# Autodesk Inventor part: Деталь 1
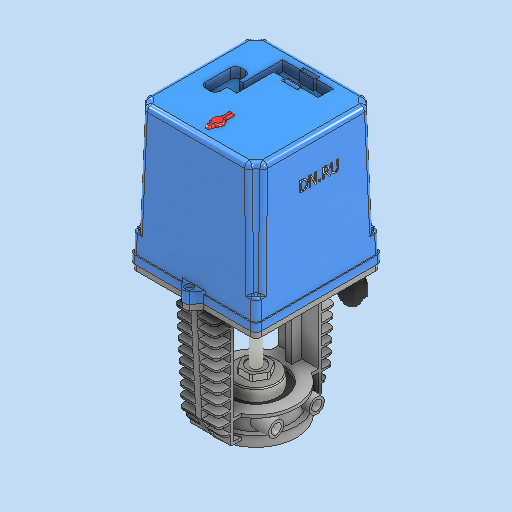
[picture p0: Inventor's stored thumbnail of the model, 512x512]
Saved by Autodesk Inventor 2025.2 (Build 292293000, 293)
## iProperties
Created: 2026-04
Part Number: Деталь 1
Material: Типовые
Document SubType Name: Modeling
Designer: igorr
Density: 1 g/cm^3
Appearance: По умолчанию
Author: igorr
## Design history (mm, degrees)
sketch "Эскиз1"
  geometry: L1 (-62.5, 62.5)-(-62.5, -62.5); L2 (-62.5, -62.5)-(62.5, -62.5); L3 (62.5, -62.5)-(62.5, 62.5); L4 (62.5, 62.5)-(-62.5, 62.5); L5 (-62.5, 62.5)-(62.5, -62.5); L6 (-62.5, -62.5)-(62.5, 62.5); L7 (0, 0)-(0, -71.5); L8 (0, -62.5)-(0, -71.5); L9 (0, 0)-(25.646, 0); L10 (0, -71.5)-(0, -61.5); C1 r 5 at (0, 66.5); 5 further points
  constraints: 20 end point, 6 midpoint, 2 parallel, 2 perpendicular, 2 point on line, 2 vertical, 1 centre point, 1 collinear, 1 symmetric about line, 4 other
  dimensions: "d0" = 125 distance of L1.start L1.end; "d1" = 125 distance of L2.end L1.end; "d2" = 71.5 distance of L7.start L7.end; "d5" = 10 distance of L7.end L10.end
extrude "Выдавливание1" new body sketch "Эскиз1" distance "d3" = 6; taper "d4" = 0 deg
chamfer "Фаска1" distance "d6" = 7.25; stored, may be unused: second distance "d7" = 2, angle "d8" = 45 deg
sketch "Эскиз2"
  geometry: L1 (-62.5, 62.5)-(-62.5, -62.5) reference; L2 (-62.5, -62.5)-(-10.25, -62.5) reference; L3 (-3.841, -69.701)-(-10.25, -62.5) reference; L4 (10.25, -62.5)-(3.841, -69.701) reference; L5 (10.25, -62.5)-(62.5, -62.5) reference; L6 (62.5, -62.5)-(62.5, 62.5) reference; L7 (62.5, 62.5)-(10.25, 62.5) reference; L8 (3.841, 69.701)-(10.25, 62.5) reference; L9 (-10.25, 62.5)-(-3.841, 69.701) reference; L10 (-10.25, 62.5)-(-62.5, 62.5) reference; L11 (61.5, 61.5)-(61.5, -61.5); L12 (61.5, -61.5)-(9.801, -61.5); L13 (9.801, -61.5)-(3.083, -69.049); L14 (-3.083, -69.049)-(-9.801, -61.5); L15 (-9.801, -61.5)-(-61.5, -61.5); L16 (-61.5, -61.5)-(-61.5, 61.5); L17 (-61.5, 61.5)-(-9.801, 61.5); L18 (-9.801, 61.5)-(-3.083, 69.049); L19 (3.083, 69.049)-(9.801, 61.5); L20 (9.801, 61.5)-(61.5, 61.5); A1 r 5 centre (0, -66.5) between (-3.841, -69.701) and (3.841, -69.701) reference; A2 r 5 centre (0, 66.5) between (3.841, 69.701) and (-3.841, 69.701) reference; A3 r 4 centre (0, -66.5) between (-3.083, -69.049) and (3.083, -69.049); A4 r 4 centre (0, 66.5) between (3.083, 69.049) and (-3.083, 69.049); 1 further point
  constraints: 20 end point, 4 point on circle, 2 centre point, 11 other
  dimensions: "d9" = 1 distance between parallel lines of L6 L11
extrude "Выдавливание2" cut sketch "Эскиз2" distance "d10" = 21; taper "d11" = 0 deg
sketch "Эскиз3"
  geometry: L1 (61.5, 61.5)-(9.801, 61.5) reference; L2 (9.801, 61.5)-(3.083, 69.049) reference; L3 (-3.083, 69.049)-(-9.801, 61.5) reference; L4 (-9.801, 61.5)-(-61.5, 61.5) reference; L5 (-61.5, 61.5)-(-61.5, -61.5) reference; L6 (-61.5, -61.5)-(-9.801, -61.5) reference; L7 (-9.801, -61.5)-(-3.083, -69.049) reference; L8 (3.083, -69.049)-(9.801, -61.5) reference; L9 (9.801, -61.5)-(61.5, -61.5) reference; L10 (61.5, -61.5)-(61.5, 61.5) reference; L11 (62.5, -62.5)-(10.25, -62.5); L12 (10.25, -62.5)-(3.841, -69.701); L13 (-3.841, -69.701)-(-10.25, -62.5); L14 (-10.25, -62.5)-(-62.5, -62.5); L15 (-62.5, -62.5)-(-62.5, 62.5); L16 (-62.5, 62.5)-(-10.25, 62.5); L17 (-10.25, 62.5)-(-3.841, 69.701); L18 (3.841, 69.701)-(10.25, 62.5); L19 (10.25, 62.5)-(62.5, 62.5); L20 (62.5, 62.5)-(62.5, -62.5); A1 r 4 centre (0, 66.5) between (3.083, 69.049) and (-3.083, 69.049) reference; A2 r 4 centre (0, -66.5) between (-3.083, -69.049) and (3.083, -69.049) reference; A3 r 5 centre (0, -66.5) between (-3.841, -69.701) and (3.841, -69.701); A4 r 5 centre (0, 66.5) between (3.841, 69.701) and (-3.841, 69.701); 1 further point
  constraints: 20 end point, 4 point on circle, 2 centre point, 11 other
  dimensions: "d12" = 1 distance between parallel lines of L9 L11
extrude "Выдавливание3" join sketch "Эскиз3" distance "d13" = 8; taper "d14" = 0 deg
sketch "Эскиз4"
  geometry: L1 (61.5, -61.5)-(61.5, 61.5); L2 (61.5, 61.5)-(-61.5, 61.5); L3 (-61.5, 61.5)-(-61.5, -61.5); L4 (-61.5, -61.5)-(61.5, -61.5); L5 (61.5, -61.5)-(-61.5, 61.5); L6 (61.5, 61.5)-(-61.5, -61.5); 1 further point
  constraints: 12 end point, 2 midpoint, 2 parallel, 1 perpendicular, 1 vertical
  dimensions: "d15" = 123 distance of L1.start L1.end; "d16" = 123 distance of L2.end L1.end
extrude "Выдавливание4" join sketch "Эскиз4" distance "d17" = 130; taper "d18" = -1 deg
sketch "Эскиз5"
  geometry: L1 (61.5, 61.5)-(61.5, -61.5) reference; L2 (61.5, -61.5)-(-61.5, -61.5) reference; L3 (-61.5, -61.5)-(-61.5, 61.5) reference; L4 (-61.5, 61.5)-(61.5, 61.5) reference; L5 (-3.841, 69.701)-(-10.25, 62.5) reference; L6 (-10.25, 62.5)-(-62.5, 62.5) reference; L7 (-62.5, 62.5)-(-62.5, -62.5) reference; L8 (-62.5, -62.5)-(-10.25, -62.5) reference; L9 (-10.25, -62.5)-(-3.841, -69.701) reference; L10 (3.841, -69.701)-(10.25, -62.5) reference; L11 (10.25, -62.5)-(62.5, -62.5) reference; L12 (62.5, -62.5)-(62.5, 62.5) reference; L13 (62.5, 62.5)-(10.25, 62.5) reference; L14 (10.25, 62.5)-(3.841, 69.701) reference; L15 (10.25, 62.5)-(14.397, 57.84); L16 (14.397, 57.84)-(-14.397, 57.84); L17 (-14.397, 57.84)-(-10.25, 62.5); L18 (62.5, 0)-(81.182, 0); L19 (10.25, -62.5)-(3.841, -69.701); L20 (-3.841, -69.701)-(-10.25, -62.5); L21 (14.397, -57.84)-(-14.397, -57.84); L22 (10.25, -62.5)-(14.397, -57.84); L23 (-14.397, -57.84)-(-10.25, -62.5); C1 r 4 at (0, 66.101); C2 r 4 at (0, -66.101); A1 r 5 centre (0, -66.5) between (-3.841, -69.701) and (3.841, -69.701) reference; A2 r 5 centre (0, 66.5) between (3.841, 69.701) and (-3.841, 69.701) reference; A3 r 5 centre (0, -66.5) between (-3.841, -69.701) and (3.841, -69.701); 1 further point
  constraints: 18 end point, 4 symmetric about line, 3 centre point, 2 horizontal, 2 point on circle, 2 point on line, 1 collinear, 1 midpoint, 2 other
  dimensions: "d19" = 8 diameter of C1
extrude "Выдавливание5" join sketch "Эскиз5" distance "d20" = 3; taper "d21" = 0 deg
sketch "Эскиз6"
  geometry: L1 (-59.231, 59.231)-(59.231, 59.231) reference; C1 r 7.5 at (59.231, 59.231); C2 r 7.5 at (-59.231, 59.231); C3 r 7.5 at (-59.231, -59.231); C4 r 7.5 at (59.231, -59.231); 1 further point
  constraints: 4 centre point, 9 other
  dimensions: "d22" = 15 diameter of C1; "d25" = 360 deg dimension on point (0, 0) L1.end (derived)
extrude "Выдавливание6" cut sketch "Эскиз6" distance "d27" = 110; taper "d28" = -2 deg
sketch "Эскиз7"
  geometry: L1 (-21.282, 47.681)-(28.718, 47.681); L2 (28.718, 47.681)-(28.718, 32.681); L3 (28.718, 32.681)-(-21.282, 32.681); L4 (-21.282, 32.681)-(-21.282, 47.681); L5 (-21.282, 47.681)-(28.718, 32.681); L6 (28.718, 47.681)-(-21.282, 32.681); L7 (-40.282, 15)-(-40.282, -10); L8 (-35.282, -15)-(-30.282, -15); L9 (-25.282, -10)-(-25.282, 15); L10 (-30.282, 20)-(-35.282, 20); L11 (-40.282, 20)-(-25.282, -15); L12 (-40.282, -15)-(-25.282, 20); L13 (-35.282, 8.5)-(-15.282, 8.5); L14 (-15.282, 8.5)-(-15.282, -3.5); L15 (-15.282, -3.5)-(-35.282, -3.5); L16 (-35.282, -3.5)-(-35.282, 8.5); L17 (-35.282, 8.5)-(-15.282, -3.5); L18 (-15.282, 8.5)-(-35.282, -3.5); L19 (-15.282, -3.5)-(-21.282, -3.5); L20 (-21.282, -3.5)-(-21.282, 50.128); L21 (-21.282, 50.128)-(-15.282, 50.128); L22 (-15.282, 50.128)-(-15.282, -3.5); L23 (-4.282, 51.181)-(-4.282, 29.181); L24 (-4.282, 29.181)-(11.718, 29.181); L25 (11.718, 29.181)-(11.718, 51.181); L26 (11.718, 51.181)-(-4.282, 51.181); L27 (-4.282, 51.181)-(11.718, 29.181); L28 (-4.282, 29.181)-(11.718, 51.181); A1 r 5 centre (-30.282, 15) between (-25.282, 15) and (-30.282, 20); A2 r 5 centre (-30.282, -10) between (-30.282, -15) and (-25.282, -10); A3 r 5 centre (-35.282, -10) between (-40.282, -10) and (-35.282, -15); A4 r 5 centre (-35.282, 15) between (-35.282, 20) and (-40.282, 15); 14 further points
  constraints: 56 end point, 10 parallel, 9 midpoint, 9 point on line, 8 point on circle, 8 tangent, 5 perpendicular, 4 centre point, 3 equal radius, 2 horizontal, 2 vertical, 1 collinear
  dimensions: "d29" = 50 distance of L1.start L1.end; "d30" = 15 distance of L1.end L2.end; "d31" = 35 distance of L11.start L12.start; "d32" = 15 distance of L11.end L12.start; "d33" = 20 distance of L13.start L13.end; "d34" = 12 distance of L13.end L14.end; "d35" = 6 distance of L14.end L19.end; "d36" = 22 distance of L23.start L23.end; "d37" = 16 distance of L24.end L23.end; "d38" = 5 radius of A1
extrude "Выдавливание7" cut sketch "Эскиз7" distance "d39" = 10; taper "d40" = 0 deg
sketch "Эскиз8"
  geometry: L1 (0, -46.285)-(0, -25.359); L2 (-15.282, 32.681)-(-15.282, -3.5) reference; L3 (3, -46.285)-(3, -25.359); L4 (-3, -25.359)-(-3, -46.285); C1 r 6 at (0, -38.032); A1 r 3 centre (0, -46.285) between (-3, -46.285) and (3, -46.285); A2 r 3 centre (0, -25.359) between (3, -25.359) and (-3, -25.359); 6 further points
  constraints: 8 end point, 4 point on circle, 4 tangent, 3 centre point, 2 parallel, 1 midpoint
  dimensions: "d41" = 12 diameter of C1; "d42" = 6 diameter of A2
extrude "Выдавливание8" join sketch "Эскиз8" distance "d43" = 2; taper "d44" = 0 deg
sketch "Эскиз9"
  geometry: L1 (-4.282, 51.181)-(11.718, 51.181) reference; L2 (11.718, 29.181)-(-4.282, 29.181) reference; L3 (11.718, 51.181)-(-4.282, 29.181); L4 (-3.282, 49.181)-(-3.282, 31.181); L5 (-3.282, 31.181)-(10.718, 31.181); L6 (10.718, 31.181)-(10.718, 49.181); L7 (10.718, 49.181)-(-3.282, 49.181); L8 (-3.282, 49.181)-(10.718, 31.181); L9 (-3.282, 31.181)-(10.718, 49.181); L10 (-3.282, 46.181)-(10.718, 46.181); L11 (10.718, 46.181)-(10.718, 34.181); L12 (10.718, 34.181)-(-3.282, 34.181); L13 (-3.282, 34.181)-(-3.282, 46.181); L14 (-3.282, 46.181)-(10.718, 34.181); L15 (10.718, 46.181)-(-3.282, 34.181); 6 further points
  constraints: 26 end point, 5 midpoint, 4 parallel, 2 perpendicular, 1 vertical
  dimensions: "d45" = 18 distance of L4.start L4.end; "d46" = 14 distance of L5.end L4.end; "d47" = 12 distance of L10.end L11.end
extrude "Выдавливание9" join sketch "Эскиз9" stored distance "d48" = 2; taper "d49" = 0 deg
sketch "Эскиз11"
  geometry: C1 r 22.5 at (0, 0); C2 r 25 at (0, 0); 1 further point
  constraints: 2 centre point, 1 coincident
  dimensions: "d50" = 45 diameter of C1; "d51" = 2.5 radial gap between concentric circles of C1 C2
extrude "Выдавливание10" cut sketch "Эскиз11" distance "d52" = 10; taper "d53" = 0 deg
sketch "Эскиз12"
  geometry: L1 (3, -61.5)-(3, 61.5); L2 (3, 61.5)-(-3, 61.5); L3 (-3, 61.5)-(-3, -61.5); L4 (-3, -61.5)-(3, -61.5); L5 (3, -61.5)-(-3, 61.5); L6 (3, 61.5)-(-3, -61.5); L7 (-9.801, 61.5)-(-61.5, 61.5) reference; L8 (3, -32.5)-(-3, -32.5); L9 (-3, -32.5)-(-3, 32.5); L10 (-3, 32.5)-(3, 32.5); L11 (3, 32.5)-(3, -32.5); L12 (3, -32.5)-(-3, 32.5); L13 (-3, -32.5)-(3, 32.5); L14 (20, -45.032)-(-20, -45.032); L15 (-20, -45.032)-(-20, -42.032); L16 (-20, -42.032)-(20, -42.032); L17 (20, -42.032)-(20, -45.032); L18 (20, -45.032)-(-20, -42.032); L19 (-20, -45.032)-(20, -42.032); L20 (-3, 0)-(-7.639, 0); L21 (20, 42.032)-(20, 45.032); L22 (-20, 42.032)-(20, 42.032); L23 (-20, 45.032)-(20, 42.032); L24 (20, 45.032)-(-20, 42.032); L25 (20, 45.032)-(-20, 45.032); L26 (-20, 45.032)-(-20, 42.032); 15 further points
  constraints: 50 end point, 9 midpoint, 7 parallel, 5 symmetric about line, 3 perpendicular, 2 collinear, 1 horizontal
  dimensions: "d54" = 6 distance of L2.end L1.end; "d55" = 65 distance of L8.end L9.end; "d58" = 40 distance of L14.start L14.end; "d59" = 3 distance of L14.end L15.end
extrude "Выдавливание11" join sketch "Эскиз12" distance "d56" = 120; taper "d57" = 0 deg
sketch "Эскиз13"
  geometry: C1 r 25 at (0, 0) reference; C2 r 40 at (0, 0); 1 further point
  constraints: 1 centre point, 1 coincident
  dimensions: "d60" = 80 diameter of C2
extrude "Выдавливание12" join sketch "Эскиз13" stored distance "d61" = 10; taper "d63" = 0 deg; dims "d62" = 2, "d64" = 0
sketch "Эскиз14"
  geometry: C1 r 40 at (0, 0) reference; C2 r 35 at (0, 0); 1 further point
  constraints: 1 centre point, 1 coincident
  dimensions: "d65" = 70 diameter of C2
extrude "Выдавливание13" join sketch "Эскиз14" distance "d66" = 15; taper "d67" = 0 deg
sketch "Эскиз15" dims "d12" = 1
  geometry: L1 (-20, 42.032)-(-20, -42.032); L2 (-20, -42.032)-(20, -42.032); L3 (20, -42.032)-(20, 42.032); L4 (20, 42.032)-(-20, 42.032); L5 (-20, 42.032)-(20, -42.032); L6 (-20, -42.032)-(20, 42.032); L7 (3, -42.032)-(20, -42.032) reference; C1 r 40 at (0, 0); C2 r 27.5 at (0, 0); A1 r 40 centre (0, 0) between (3, -39.887) and (3, 39.887) reference; 5 further points
  constraints: 12 end point, 2 centre point, 2 coincident, 2 midpoint, 2 parallel, 1 collinear, 1 concentric, 1 perpendicular, 1 vertical
  dimensions: "d68" = 40 distance of L2.end L1.end; "d69" = 55 diameter of C2
extrude "Выдавливание14" join sketch "Эскиз15" distance "d70" = 3; taper "d71" = 0 deg
sketch "Эскиз16"
  geometry: L1 (20, 42.032)-(20, -42.032); L2 (20, -42.032)-(-20, -42.032); L3 (-20, -42.032)-(-20, 42.032); L4 (-20, 42.032)-(20, 42.032); L5 (20, 42.032)-(-20, -42.032); L6 (20, -42.032)-(-20, 42.032); A1 r 40 centre (0, 0) between (-20, 34.641) and (-20, -34.641) reference; 1 further point
  constraints: 12 end point, 2 midpoint, 2 parallel, 1 perpendicular, 1 vertical
extrude "Выдавливание15" join sketch "Эскиз16" distance "d72" = 3; taper "d73" = 0 deg
sketch "Эскиз17"
  geometry: L1 (0, -61.5)-(-120, -61.5) reference; L2 (0, -61.5)-(-9, -61.5); L3 (0, -42.032)-(-97, -42.032) reference; L4 (-9, -61.5)-(-9, -42.032); L5 (-9, -42.032)-(-11, -42.032); L6 (-11, -42.032)-(-11, -61.5); L7 (-11, -61.5)-(-9, -61.5); 3 further points
  constraints: 10 end point, 2 parallel, 2 point on line, 1 perpendicular, 1 vertical
  dimensions: "d74" = 9 distance of L1.start L2.end; "d75" = 2 distance of L5.end L4.end
extrude "Выдавливание16" join sketch "Эскиз17" stored distance "d76" = 40; taper "d77" = 0 deg
pattern_linear "Прямоуг.массив1"
mirror "Зеркальное отражение1"
sketch "Эскиз18"
  geometry: L1 (10.391, 0)-(0, 0) reference; L2 (0, 0)-(-11.293, 18.805); L3 (-16.468, 120)-(-16.468, 111) reference; L4 (-11.293, 18.805)-(-16.468, 120); L5 (0, 0)-(-16.468, 0) reference; L6 (-16.468, 120)-(-16.468, 0); L7 (-16.468, 0)-(0, 0); L8 (45.032, 120)-(45.032, 160.583); L9 (79.673, 0)-(90.064, 0); L10 (90.064, 0)-(101.357, 18.805); L11 (106.532, 120)-(106.532, 111); L12 (101.357, 18.805)-(106.532, 120); L13 (90.064, 0)-(106.532, 0); L14 (106.532, 120)-(106.532, 0); L15 (106.532, 0)-(90.064, 0); 2 further points
  constraints: 24 end point, 6 symmetric about line, 2 perpendicular, 1 vertical
extrude "Выдавливание17" cut sketch "Эскиз18" distance "d81" = 40; taper "d82" = 0 deg
sketch "Эскиз19"
  geometry: C1 r 27.5 at (0, 0) reference; C2 r 21 at (0, 0); 1 further point
  constraints: 1 centre point, 1 coincident
  dimensions: "d83" = 42 diameter of C2
extrude "Выдавливание18" join sketch "Эскиз19" distance "d84" = 12; taper "d85" = 0 deg
sketch "Эскиз20"
  geometry: L1 (13.424, 0)-(6.712, -11.626); L2 (6.712, -11.626)-(-6.712, -11.626); L3 (-6.712, -11.626)-(-13.424, 0); L4 (-13.424, 0)-(-6.712, 11.626); L5 (-6.712, 11.626)-(6.712, 11.626); L6 (6.712, 11.626)-(13.424, 0); 2 further points
  constraints: 12 end point, 1 coincident, 13 other
extrude "Выдавливание19" join sketch "Эскиз20" distance "d86" = 6; taper "d87" = 0 deg
sketch "Эскиз21"
  geometry: C1 r 9 at (0, 0); 1 further point
  constraints: 1 centre point, 1 coincident
  dimensions: "d88" = 18 diameter of C1
extrude "Выдавливание20" cut sketch "Эскиз21" distance "d89" = 1; taper "d90" = 0 deg
sketch "Эскиз22"
  geometry: C1 r 5 at (0, 0); 1 further point
  constraints: 1 centre point, 1 coincident
  dimensions: "d91" = 10 diameter of C1
extrude "Выдавливание21" join sketch "Эскиз22" distance "d92" = 48; taper "d93" = 0 deg
sketch "Эскиз23"
  geometry: C1 r 6.5 at (0, 0); 1 further point
  constraints: 1 centre point, 1 coincident
  dimensions: "d94" = 13 diameter of C1
extrude "Выдавливание22" join sketch "Эскиз23" distance "d95" = 15; taper "d96" = 0 deg
sketch "Эскиз24"
  geometry: L1 (-11.771, -15)-(-28.52, -15); L2 (-28.52, -15)-(-28.52, 15); L3 (-28.52, 15)-(-11.771, 15); L4 (-11.771, 15)-(-11.771, -15); L5 (-20, -6.5)-(-20, 6.5) reference; L6 (-11.771, -15)-(-28.52, 15); L7 (-28.52, -15)-(-11.771, 15); 2 further points
  constraints: 12 end point, 3 parallel, 2 midpoint, 1 perpendicular
  dimensions: "d97" = 30 distance of L1.end L2.end
extrude "Выдавливание23" join sketch "Эскиз24" stored distance "d98" = 8; taper "d99" = 0 deg
sketch "Эскиз25"
  geometry: L1 (-0.5, 21)-(8.5, 21); L2 (8.5, 21)-(8.5, 9); L3 (8.5, 9)-(-0.5, 9); L4 (-0.5, 9)-(-0.5, 21); L5 (-0.5, 21)-(8.5, 9); L6 (8.5, 21)-(-0.5, 9); A1 r 6.5 centre (4, 15) between (0, 20.123) and (0, 9.877) reference; 1 further point
  constraints: 12 end point, 2 midpoint, 2 parallel, 1 horizontal, 1 perpendicular
  dimensions: "d100" = 9 distance of L1.start L1.end; "d101" = 12 distance of L1.end L2.end
extrude "Выдавливание24" join sketch "Эскиз25" distance "d102" = 15; taper "d103" = 0 deg
sketch "Эскиз26"
  geometry: L1 (-1, -2.664)-(13, -2.664); L2 (13, -2.664)-(13, 4.336); L3 (6, 11.336)-(6, 11.336); L4 (-1, 4.336)-(-1, -2.664); L5 (-1, -2.664)-(13, 11.336); L6 (13, -2.664)-(-1, 11.336); A1 r 7 centre (6, 4.336) between (6, 11.336) and (-1, 4.336); A2 r 7 centre (6, 4.336) between (13, 4.336) and (6, 11.336); 3 further points
  constraints: 12 end point, 4 point on circle, 4 point on line, 4 tangent, 2 centre point, 2 midpoint, 2 parallel, 1 concentric, 1 horizontal, 1 perpendicular
  dimensions: "d104" = 14 distance of L1.start L1.end; "d105" = 14 distance of L5.end L1.end; "d106" = 7 radius of A1
extrude "Выдавливание25" join sketch "Эскиз26" distance "d107" = 2; taper "d108" = 0 deg
sketch "Эскиз27"
  geometry: L1 (-7, -14.435)-(7, -14.435) reference; L2 (-7, -14.435)-(7, -14.435); L3 (7, -14.435)-(7, -11.771); L4 (7, -11.771)-(-7, -11.771); L5 (-7, -11.771)-(-7, -14.435); 1 further point
  constraints: 8 end point, 3 equal length, 1 perpendicular
extrude "Выдавливание26" join sketch "Эскиз27" stored distance "d109" = 2; taper "d110" = 0 deg
mirror "Зеркальное отражение2"
sketch "Эскиз31"
  geometry: L1 (-100, -34.871)-(-115, -34.871) reference; L2 (-107.5, -34.871)-(-107.5, 34.871); L3 (-100, 34.871)-(-115, 34.871) reference; C1 r 7.5 at (-107.5, 0); C2 r 5 at (-107.5, 0); 1 further point
  constraints: 3 midpoint, 2 centre point, 2 end point, 1 coincident
  dimensions: "d117" = 10 diameter of C2
extrude "Выдавливание30" join sketch "Эскиз31" distance "d118" = 40; taper "d119" = 0 deg
sketch "Эскиз32"
  geometry: L1 (-100, 34.871)-(-115, 34.871) reference; L2 (-107.5, 34.871)-(-107.5, -34.871); L3 (-115, -34.871)-(-100, -34.871) reference; L4 (-100, 0)-(-100, 34.871) reference; L5 (-97, 27.5)-(-97, -27.5) reference; L6 (-97, 0)-(-91.595, 0); C1 r 7.5 at (-107.5, 20.02); C2 r 5 at (-107.5, 20.02); C3 r 7.5 at (-107.5, -20.02); C4 r 5 at (-107.5, -20.02); 1 further point
  constraints: 4 centre point, 4 end point, 4 midpoint, 2 coincident, 2 symmetric about line, 1 horizontal, 1 point on line, 1 tangent, 2 other
  dimensions: "d120" = 10 diameter of C2
extrude "Выдавливание31" join sketch "Эскиз32" distance "d121" = 40; taper "d122" = 0 deg
sketch "Эскиз33"
  geometry: L1 (58.359, -47.515)-(52.809, -56.952); L2 (52.809, -56.952)-(41.862, -56.863); L3 (41.862, -56.863)-(36.465, -47.338); L4 (36.465, -47.338)-(42.015, -37.902); L5 (42.015, -37.902)-(52.963, -37.991); L6 (52.963, -37.991)-(58.359, -47.515); L7 (45.512, 27.742)-(45.512, 7.03); L8 (45.512, 7.03)-(57.512, 7.03); L9 (57.512, 7.03)-(57.512, 27.742); L10 (57.512, 27.742)-(45.512, 27.742); L11 (45.512, 27.742)-(57.512, 7.03); L12 (45.512, 7.03)-(57.512, 27.742); C1 r 10 at (47.412, 43.457); 3 further points
  constraints: 24 end point, 2 midpoint, 2 parallel, 1 centre point, 1 perpendicular, 1 vertical, 13 other
  dimensions: "d123" = 20 diameter of C1; "d124" = 12 distance of L8.end L7.end
extrude "Выдавливание32" join sketch "Эскиз33" distance "d125" = 3; taper "d126" = 0 deg
node "Непосредственное редактирование1"
sketch "Эскиз34"
  geometry: L1 (10.948, 0)-(0, 0) reference; L2 (10.948, -18.962)-(0, -18.962) reference; L3 (10.948, 0)-(0, -18.962); C1 r 7.5 at (5.474, -9.481); 1 further point
  constraints: 2 end point, 1 centre point, 1 midpoint
  dimensions: "d130" = 15 diameter of C1
extrude "Выдавливание33" join sketch "Эскиз34" distance "d131" = 5; taper "d132" = 0 deg
sketch "Эскиз35"
  geometry: L1 (9.679, -5.536)-(0.046, -11.15); L2 (0.046, -11.15)-(-9.634, -5.615); L3 (-9.634, -5.615)-(-9.679, 5.536); L4 (-9.679, 5.536)-(-0.046, 11.15); L5 (-0.046, 11.15)-(9.634, 5.615); L6 (9.634, 5.615)-(9.679, -5.536); C1 r 7.5 at (0, 0) reference; 2 further points
  constraints: 12 end point, 1 coincident, 13 other
extrude "Выдавливание34" join sketch "Эскиз35" distance "d133" = 12; taper "d134" = 0 deg
sketch "Эскиз36"
  geometry: C1 r 9 at (0, 0); C2 r 7.5 at (0, 0) reference; C3 r 4 at (0, 0); 1 further point
  constraints: 2 centre point, 1 coincident
  dimensions: "d135" = 18 diameter of C1; "d136" = 8 diameter of C3
extrude "Выдавливание35" join sketch "Эскиз36" distance "d137" = 8; taper "d138" = 0 deg
sketch "Эскиз37"
  geometry: L1 (43.658, 99.007)-(55.919, 99.007); L2 (55.919, 99.007)-(55.919, 95.895); L3 (55.919, 95.895)-(43.658, 95.895); L4 (43.658, 95.895)-(43.658, 99.007); 1 further point
  constraints: 2 other
feature "Рельеф1" sketch "Эскиз37" dims "d139" = 0.5, "d140" = 0
fillet "Сопряжение1" dims "d145" = 5
fillet "Сопряжение2" dims "d146" = 2
fillet "Сопряжение3" dims "d147" = 4
fillet "Сопряжение4" dims "d148" = 2
sketch "Эскиз40"
  geometry: C1 r 2.5 at (-7.435, 0); A1 r 7 centre (-7.435, 0) between (-7.435, -7) and (-7.435, 7) reference; 1 further point
  constraints: 1 centre point, 1 coincident
  dimensions: "d149" = 5 diameter of C1
extrude "Выдавливание38" join sketch "Эскиз40" stored distance "d150" = 25; taper "d151" = 0 deg
sketch "Эскиз41"
  geometry: L1 (5, -35)-(-5, -35) reference; L2 (0, -35)-(0, -34.078); C1 r 3 at (-10.145, -22.095); C2 r 3 at (10.145, -22.095); 1 further point
  constraints: 2 centre point, 2 end point, 1 midpoint, 1 symmetric about line, 1 vertical, 1 other
  dimensions: "d152" = 6 diameter of C1
extrude "Выдавливание39" cut sketch "Эскиз41" stored distance "d153" = 25; taper "d154" = 0 deg
sketch "Эскиз42"
  geometry: C1 r 27.5 at (0, 0) reference; 1 further point
extrude "Выдавливание40" cut sketch "Эскиз42" distance "d155" = 3; taper "d156" = 0 deg
chamfer "Фаска2" distance "d161" = 1; stored, may be unused: second distance "d162" = 2, angle "d163" = 45 deg
node "Твердое тело1"
node "Спроецированная петля1"
node "Спроецированная петля2"
node "Спроецированная петля3"
node "Эскиз — круговой массив1" dims "d25" = 360 deg (derived)
feature "Перенос1" dims "d129" = 2
other parameters: "d127" = 0, "d128" = 0
